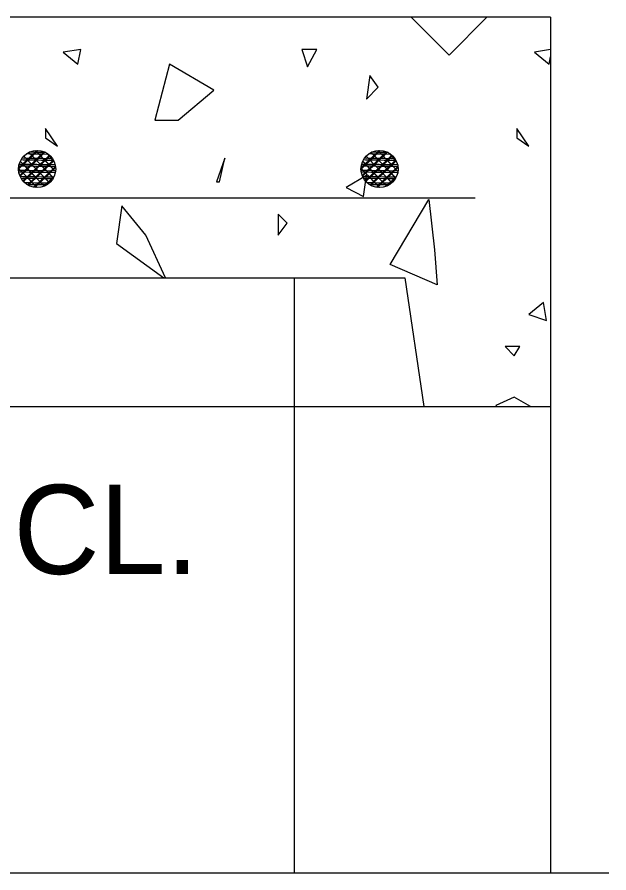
# Model space of a CAD drawing. Extents: x 26.41 to 33.74, y 20.66 to 30.6.
# Drawn here: x 32.985 to 33.383, y 27.258 to 27.834 of the extents above; entities that cross this region are included whole.
import ezdxf

# ---------------------------------------------------------------- set-up
doc = ezdxf.new("R2010")
doc.units = 0
for name, color, linetype in [('DETL-LINE', 7, 'Continuous'), ('DETL-NOTE', 7, 'Continuous'), ('DETL-PATT', 7, 'Continuous')]:
    doc.layers.add(name, color=color, linetype=linetype)

msp = doc.modelspace()

# ---------------------------------------------------------------- linework, layer by layer
at = {"layer": 'DETL-LINE'}
for p, q in [((33.34406, 27.83377), (31.7863, 27.83377)), ((33.34406, 27.83377), (33.34406, 27.25786)), ((32.99743, 27.74341), (32.98792, 27.73425)), ((32.9979, 27.74313), (32.98835, 27.73397)), ((32.9935, 27.74183), (33.00266, 27.73232)), ((32.99931, 27.74171), (33.00851, 27.7322)), ((33.22803, 27.74341), (33.21852, 27.73425)), ((33.22851, 27.74313), (33.21895, 27.73397)), ((33.2241, 27.74183), (33.23326, 27.73232)), ((33.22992, 27.74171), (33.23912, 27.7322)), ((32.98756, 27.73613), (32.99672, 27.72658)), ((32.99735, 27.73759), (32.9878, 27.72839)), ((32.99778, 27.73727), (32.98827, 27.72812)), ((33.00218, 27.73735), (32.98894, 27.73759)), ((33.00222, 27.73853), (32.98898, 27.73877)), ((32.99051, 27.73896), (32.99971, 27.72945)), ((33.0003, 27.74046), (32.99078, 27.73126)), ((33.00077, 27.74014), (32.99122, 27.73098)), ((33.00631, 27.73727), (32.99306, 27.73751)), ((33.00635, 27.73845), (32.9931, 27.73869)), ((32.99338, 27.73602), (33.00258, 27.72646)), ((33.00317, 27.73751), (32.99365, 27.72827)), ((33.00364, 27.73719), (32.99405, 27.728)), ((32.99633, 27.73885), (33.00552, 27.72933)), ((33.00615, 27.74038), (32.99664, 27.73114)), ((33.00659, 27.74006), (32.99703, 27.73087)), ((32.9992, 27.73594), (33.00839, 27.72635)), ((33.00902, 27.73739), (32.99947, 27.72819)), ((33.00942, 27.73708), (32.9999, 27.72788)), ((33.21817, 27.73613), (33.22733, 27.72658)), ((33.22795, 27.73759), (33.2184, 27.72839)), ((33.22839, 27.73727), (33.21888, 27.72812)), ((33.23279, 27.73735), (33.21954, 27.73759)), ((33.23283, 27.73853), (33.21958, 27.73877)), ((33.22112, 27.73896), (33.23031, 27.72945)), ((33.2309, 27.74046), (33.22139, 27.73126)), ((33.23137, 27.74014), (33.22182, 27.73098)), ((33.23692, 27.73727), (33.22367, 27.73751)), ((33.23696, 27.73845), (33.22371, 27.73869)), ((33.22399, 27.73602), (33.23318, 27.72646)), ((33.23377, 27.73751), (33.22426, 27.72827)), ((33.23424, 27.73719), (33.22465, 27.728)), ((33.22693, 27.73885), (33.23613, 27.72933)), ((33.23676, 27.74038), (33.22725, 27.73114)), ((33.23719, 27.74006), (33.22764, 27.73087)), ((33.2298, 27.73594), (33.239, 27.72635)), ((33.23963, 27.73739), (33.23008, 27.72819)), ((33.24002, 27.73708), (33.23051, 27.72788)), ((32.98744, 27.73028), (32.9966, 27.72076)), ((33.00207, 27.73028), (32.98882, 27.73051)), ((33.0021, 27.73322), (32.98886, 27.73346)), ((33.00214, 27.7344), (32.9889, 27.73464)), ((32.99043, 27.73315), (32.99959, 27.72359)), ((33.00022, 27.73464), (32.99067, 27.72544)), ((33.00065, 27.73433), (32.99114, 27.72513)), ((33.00619, 27.7302), (32.99295, 27.73043)), ((33.00623, 27.73315), (32.99299, 27.73338)), ((33.00627, 27.73433), (32.99303, 27.73456)), ((32.99326, 27.7302), (33.00246, 27.72065)), ((33.00309, 27.73165), (32.99354, 27.72249)), ((33.00352, 27.73134), (32.99397, 27.72214)), ((32.99621, 27.73307), (33.00545, 27.72348)), ((33.00604, 27.73452), (32.99652, 27.72532)), ((33.00647, 27.73421), (32.99692, 27.72501)), ((33.01032, 27.73012), (32.99707, 27.73036)), ((33.01036, 27.73307), (32.99711, 27.7333)), ((33.0104, 27.73425), (32.99715, 27.73448)), ((33.0089, 27.73153), (32.99935, 27.72238)), ((33.00934, 27.73122), (32.99979, 27.72206)), ((33.21805, 27.73028), (33.22721, 27.72076)), ((33.23267, 27.73028), (33.21943, 27.73051)), ((33.23271, 27.73322), (33.21946, 27.73346)), ((33.23275, 27.7344), (33.2195, 27.73464)), ((33.22104, 27.73315), (33.2302, 27.72359)), ((33.23082, 27.73464), (33.22127, 27.72544)), ((33.23126, 27.73433), (33.22174, 27.72513)), ((33.2368, 27.7302), (33.22355, 27.73043)), ((33.23684, 27.73315), (33.22359, 27.73338)), ((33.23688, 27.73433), (33.22363, 27.73456)), ((33.22387, 27.7302), (33.23306, 27.72065)), ((33.23369, 27.73165), (33.22414, 27.72249)), ((33.23413, 27.73134), (33.22457, 27.72214)), ((33.22682, 27.73307), (33.23605, 27.72348)), ((33.23664, 27.73452), (33.22713, 27.72532)), ((33.23707, 27.73421), (33.22752, 27.72501)), ((33.24093, 27.73012), (33.22768, 27.73036)), ((33.24097, 27.73307), (33.22772, 27.7333)), ((33.241, 27.73425), (33.22776, 27.73448)), ((33.23951, 27.73153), (33.22996, 27.72238)), ((33.23994, 27.73122), (33.23039, 27.72206)), ((33.00195, 27.72497), (32.9887, 27.72521)), ((33.00199, 27.72615), (32.98874, 27.72639)), ((33.00203, 27.7291), (32.98878, 27.72933)), ((33.00607, 27.72489), (32.99283, 27.72513)), ((33.00611, 27.72607), (32.99287, 27.72631)), ((33.00615, 27.72902), (32.99291, 27.72925)), ((33.00596, 27.72867), (32.99641, 27.71951)), ((33.00635, 27.72839), (32.99684, 27.71919)), ((33.01028, 27.72894), (32.99703, 27.72918)), ((33.23255, 27.72497), (33.21931, 27.72521)), ((33.23259, 27.72615), (33.21935, 27.72639)), ((33.23263, 27.7291), (33.21939, 27.72933)), ((33.23668, 27.72489), (33.22343, 27.72513)), ((33.23672, 27.72607), (33.22347, 27.72631)), ((33.23676, 27.72902), (33.22351, 27.72925)), ((33.23656, 27.72867), (33.22701, 27.71951)), ((33.23696, 27.72839), (33.22744, 27.71919)), ((33.24089, 27.72894), (33.22764, 27.72918)), ((33.00604, 27.72194), (32.99279, 27.72218)), ((33.23664, 27.72194), (33.2234, 27.72218)), ((33.29328, 27.71188), (32.55162, 27.71188)), ((31.86633, 27.65839), (33.24596, 27.65839)), ((33.17167, 27.25786), (33.17167, 27.65839)), ((33.24596, 27.65831), (33.25865, 27.5718)), ((31.85811, 27.57172), (33.25865, 27.5718)), ((33.25865, 27.5718), (33.34406, 27.5718)), ((32.72968, 27.25786), (33.38337, 27.25786))]:
    msp.add_line(p, q, dxfattribs=at)
for points in [[(32.99806, 27.74399), (32.9909, 27.73712)], [(33.00226, 27.74148), (32.99106, 27.74168)], [(32.99813, 27.74156), (32.99106, 27.74168)], [(32.99401, 27.74164), (32.99106, 27.74168)], [(32.99876, 27.74399), (32.99134, 27.7368)], [(32.99267, 27.7427), (32.99983, 27.73531)], [(33.00226, 27.74262), (32.99295, 27.74282)], [(32.99817, 27.7427), (32.99295, 27.74282)], [(32.99405, 27.74278), (32.99295, 27.74282)], [(33.00592, 27.7414), (32.99314, 27.74164)], [(33.00407, 27.74262), (32.99318, 27.74282)], [(33.00301, 27.74309), (32.99377, 27.73413)], [(32.99806, 27.74399), (32.99389, 27.73999)], [(33.00356, 27.74285), (32.99417, 27.73385)], [(32.99876, 27.74399), (32.99428, 27.73967)], [(33.00301, 27.74309), (32.99676, 27.737)], [(33.00356, 27.74285), (32.99715, 27.73668)], [(32.99719, 27.74396), (33.00277, 27.73814)], [(32.99719, 27.74396), (33.00564, 27.73519)], [(33.00592, 27.7414), (32.99727, 27.74156)], [(33.00407, 27.74262), (32.99731, 27.74274)], [(33.00592, 27.7414), (33.0014, 27.74148)], [(33.00407, 27.74262), (33.00144, 27.74266)], [(33.00438, 27.74246), (33.00576, 27.74101)], [(33.00438, 27.74246), (33.00863, 27.73806)], [(33.00438, 27.74246), (33.00945, 27.73719)], [(33.00517, 27.74164), (33.00945, 27.73719)], [(33.22866, 27.74399), (33.22151, 27.73712)], [(33.23287, 27.74148), (33.22167, 27.74168)], [(33.22874, 27.74156), (33.22167, 27.74168)], [(33.22461, 27.74164), (33.22167, 27.74168)], [(33.22937, 27.74399), (33.22194, 27.7368)], [(33.22328, 27.7427), (33.23043, 27.73531)], [(33.23287, 27.74262), (33.22355, 27.74282)], [(33.22878, 27.7427), (33.22355, 27.74282)], [(33.22465, 27.74278), (33.22355, 27.74282)], [(33.23652, 27.7414), (33.22375, 27.74164)], [(33.23468, 27.74262), (33.22379, 27.74282)], [(33.23361, 27.74309), (33.22438, 27.73413)], [(33.22866, 27.74399), (33.2245, 27.73999)], [(33.23417, 27.74285), (33.22477, 27.73385)], [(33.22937, 27.74399), (33.22489, 27.73967)], [(33.23361, 27.74309), (33.22737, 27.737)], [(33.23417, 27.74285), (33.22776, 27.73668)], [(33.2278, 27.74396), (33.23338, 27.73814)], [(33.2278, 27.74396), (33.23625, 27.73519)], [(33.23652, 27.7414), (33.22788, 27.74156)], [(33.23468, 27.74262), (33.22792, 27.74274)], [(33.23652, 27.7414), (33.232, 27.74148)], [(33.23468, 27.74262), (33.23204, 27.74266)], [(33.23499, 27.74246), (33.23637, 27.74101)], [(33.23499, 27.74246), (33.23924, 27.73806)], [(33.23499, 27.74246), (33.24006, 27.73719)], [(33.23578, 27.74164), (33.24006, 27.73719)], [(32.99491, 27.74026), (32.98583, 27.73153)], [(32.99192, 27.73739), (32.98583, 27.73153)], [(32.99448, 27.74058), (32.98587, 27.73224)], [(32.99149, 27.73771), (32.98587, 27.73224)], [(32.98697, 27.73672), (32.99385, 27.72957)], [(32.99806, 27.73743), (32.98744, 27.73763)], [(32.99393, 27.73751), (32.98744, 27.73763)], [(32.9898, 27.73759), (32.98744, 27.73763)], [(32.9981, 27.73857), (32.98815, 27.73877)], [(32.99397, 27.73865), (32.98815, 27.73877)], [(32.98984, 27.73873), (32.98815, 27.73877)], [(32.98933, 27.74018), (32.99684, 27.73244)], [(33.00942, 27.73719), (32.99719, 27.73743)], [(33.00871, 27.73837), (32.99723, 27.73861)], [(33.00662, 27.74081), (32.99959, 27.73401)], [(33.00702, 27.7405), (33.00002, 27.73374)], [(33.00942, 27.73719), (33.00132, 27.73735)], [(33.00871, 27.73837), (33.00136, 27.73853)], [(33.00218, 27.73877), (33.01063, 27.72996)], [(33.00922, 27.73755), (33.00246, 27.73106)], [(33.00945, 27.73712), (33.00289, 27.73075)], [(33.00505, 27.73582), (33.01063, 27.72996)], [(33.008, 27.73865), (33.00945, 27.73719)], [(33.22552, 27.74026), (33.21644, 27.73153)], [(33.22253, 27.73739), (33.21644, 27.73153)], [(33.22509, 27.74058), (33.21648, 27.73224)], [(33.2221, 27.73771), (33.21648, 27.73224)], [(33.21758, 27.73672), (33.22446, 27.72957)], [(33.22866, 27.73743), (33.21805, 27.73763)], [(33.22454, 27.73751), (33.21805, 27.73763)], [(33.22041, 27.73759), (33.21805, 27.73763)], [(33.2287, 27.73857), (33.21876, 27.73877)], [(33.22457, 27.73865), (33.21876, 27.73877)], [(33.22045, 27.73873), (33.21876, 27.73877)], [(33.21994, 27.74018), (33.22744, 27.73244)], [(33.24002, 27.73719), (33.2278, 27.73743)], [(33.23931, 27.73837), (33.22784, 27.73861)], [(33.23723, 27.74081), (33.2302, 27.73401)], [(33.23762, 27.7405), (33.23063, 27.73374)], [(33.24002, 27.73719), (33.23192, 27.73735)], [(33.23931, 27.73837), (33.23196, 27.73853)], [(33.23279, 27.73877), (33.24124, 27.72996)], [(33.23983, 27.73755), (33.23306, 27.73106)], [(33.24006, 27.73712), (33.2335, 27.73075)], [(33.23566, 27.73582), (33.24124, 27.72996)], [(33.23861, 27.73865), (33.24006, 27.73719)], [(32.98898, 27.73452), (32.98583, 27.73153)], [(32.98583, 27.73193), (32.99086, 27.7267)], [(32.98583, 27.73193), (32.99373, 27.72371)], [(32.98599, 27.73165), (32.98583, 27.73153)], [(32.98854, 27.73484), (32.98587, 27.73224)], [(32.99794, 27.73036), (32.98587, 27.73055)], [(32.99381, 27.73043), (32.98587, 27.73055)], [(32.98968, 27.73047), (32.98587, 27.73055)], [(32.99798, 27.7333), (32.98603, 27.7335)], [(32.99385, 27.73338), (32.98603, 27.7335)], [(32.98972, 27.73346), (32.98603, 27.7335)], [(32.99802, 27.73448), (32.98626, 27.73468)], [(32.99389, 27.73452), (32.98626, 27.73468)], [(32.98976, 27.7346), (32.98626, 27.73468)], [(32.99436, 27.73472), (32.98658, 27.72725)], [(32.99137, 27.73189), (32.98658, 27.72725)], [(32.99479, 27.7344), (32.98681, 27.72674)], [(32.99185, 27.73153), (32.98681, 27.72674)], [(32.99723, 27.73177), (32.9887, 27.72356)], [(32.99766, 27.73146), (32.98906, 27.72316)], [(32.99908, 27.73008), (33.00662, 27.72226)], [(33.01067, 27.73012), (33.0012, 27.73028)], [(33.01067, 27.73307), (33.00124, 27.73322)], [(33.01048, 27.73425), (33.00128, 27.7344)], [(33.00207, 27.73295), (33.00922, 27.72552)], [(33.01063, 27.73319), (33.00234, 27.72525)], [(33.01071, 27.73256), (33.00277, 27.72493)], [(33.00493, 27.72996), (33.00922, 27.72552)], [(33.01063, 27.73319), (33.00533, 27.72808)], [(33.01071, 27.73256), (33.00576, 27.7278)], [(33.00792, 27.73283), (33.01063, 27.72996)], [(33.21958, 27.73452), (33.21644, 27.73153)], [(33.21644, 27.73193), (33.22147, 27.7267)], [(33.21644, 27.73193), (33.22434, 27.72371)], [(33.2166, 27.73165), (33.21644, 27.73153)], [(33.21915, 27.73484), (33.21648, 27.73224)], [(33.22854, 27.73036), (33.21648, 27.73055)], [(33.22442, 27.73043), (33.21648, 27.73055)], [(33.22029, 27.73047), (33.21648, 27.73055)], [(33.22858, 27.7333), (33.21663, 27.7335)], [(33.22446, 27.73338), (33.21663, 27.7335)], [(33.22033, 27.73346), (33.21663, 27.7335)], [(33.22862, 27.73448), (33.21687, 27.73468)], [(33.2245, 27.73452), (33.21687, 27.73468)], [(33.22037, 27.7346), (33.21687, 27.73468)], [(33.22497, 27.73472), (33.21719, 27.72725)], [(33.22198, 27.73189), (33.21719, 27.72725)], [(33.2254, 27.7344), (33.21742, 27.72674)], [(33.22245, 27.73153), (33.21742, 27.72674)], [(33.22784, 27.73177), (33.21931, 27.72356)], [(33.22827, 27.73146), (33.21966, 27.72316)], [(33.22968, 27.73008), (33.23723, 27.72226)], [(33.24128, 27.73012), (33.23181, 27.73028)], [(33.24128, 27.73307), (33.23185, 27.73322)], [(33.24108, 27.73425), (33.23189, 27.7344)], [(33.23267, 27.73295), (33.23983, 27.72552)], [(33.24124, 27.73319), (33.23295, 27.72525)], [(33.24132, 27.73256), (33.23338, 27.72493)], [(33.23554, 27.72996), (33.23983, 27.72552)], [(33.24124, 27.73319), (33.23593, 27.72808)], [(33.24132, 27.73256), (33.23637, 27.7278)], [(33.23853, 27.73283), (33.24124, 27.72996)], [(32.9979, 27.72918), (32.98603, 27.72937)], [(32.99377, 27.72925), (32.98603, 27.72937)], [(32.98964, 27.72933), (32.98603, 27.72937)], [(32.98843, 27.72902), (32.98658, 27.72725)], [(32.98886, 27.7287), (32.98681, 27.72674)], [(32.99786, 27.72623), (32.98693, 27.72642)], [(32.99373, 27.72631), (32.98693, 27.72642)], [(32.98961, 27.72635), (32.98693, 27.72642)], [(32.99782, 27.72505), (32.98756, 27.72525)], [(32.99369, 27.72513), (32.98756, 27.72525)], [(32.98957, 27.72521), (32.98756, 27.72525)], [(32.99424, 27.7289), (32.9887, 27.72356)], [(32.9913, 27.72603), (32.9887, 27.72356)], [(32.99468, 27.72863), (32.98906, 27.72316)], [(32.99173, 27.72576), (32.98906, 27.72316)], [(32.99031, 27.72733), (32.99821, 27.71907)], [(33.0001, 27.72878), (32.99189, 27.72084)], [(32.99711, 27.72591), (32.99189, 27.72084)], [(33.00053, 27.72851), (32.99236, 27.72061)], [(32.99755, 27.72564), (32.99236, 27.72061)], [(32.99318, 27.72434), (32.99821, 27.71907)], [(32.99613, 27.72721), (33.00305, 27.72002)], [(33.00297, 27.7258), (32.99613, 27.71927)], [(33.0034, 27.72552), (32.99684, 27.71919)], [(33.00879, 27.72485), (32.99696, 27.72505)], [(33.00945, 27.72599), (32.997, 27.72623)], [(32.999, 27.72422), (33.00305, 27.72002)], [(33.00879, 27.72485), (33.00108, 27.72497)], [(33.00945, 27.72599), (33.00112, 27.72615)], [(33.01048, 27.72894), (33.00116, 27.7291)], [(33.00195, 27.72709), (33.00662, 27.72226)], [(33.00977, 27.72666), (33.00273, 27.7199)], [(33.00883, 27.72572), (33.00273, 27.7199)], [(33.0091, 27.72529), (33.00415, 27.72053)], [(33.0091, 27.72529), (33.00415, 27.72053)], [(33.00977, 27.72666), (33.00521, 27.72226)], [(33.0091, 27.72529), (33.00564, 27.72194)], [(33.0078, 27.72698), (33.00922, 27.72552)], [(33.00977, 27.72666), (33.0082, 27.72513)], [(33.0091, 27.72529), (33.00863, 27.72481)], [(33.22851, 27.72918), (33.21663, 27.72937)], [(33.22438, 27.72925), (33.21663, 27.72937)], [(33.22025, 27.72933), (33.21663, 27.72937)], [(33.21903, 27.72902), (33.21719, 27.72725)], [(33.21946, 27.7287), (33.21742, 27.72674)], [(33.22847, 27.72623), (33.21754, 27.72642)], [(33.22434, 27.72631), (33.21754, 27.72642)], [(33.22021, 27.72635), (33.21754, 27.72642)], [(33.22843, 27.72505), (33.21817, 27.72525)], [(33.2243, 27.72513), (33.21817, 27.72525)], [(33.22017, 27.72521), (33.21817, 27.72525)], [(33.22485, 27.7289), (33.21931, 27.72356)], [(33.2219, 27.72603), (33.21931, 27.72356)], [(33.22528, 27.72863), (33.21966, 27.72316)], [(33.22233, 27.72576), (33.21966, 27.72316)], [(33.22092, 27.72733), (33.22882, 27.71907)], [(33.23071, 27.72878), (33.22249, 27.72084)], [(33.22772, 27.72591), (33.22249, 27.72084)], [(33.23114, 27.72851), (33.22296, 27.72061)], [(33.22815, 27.72564), (33.22296, 27.72061)], [(33.22379, 27.72434), (33.22882, 27.71907)], [(33.22674, 27.72721), (33.23365, 27.72002)], [(33.23358, 27.7258), (33.22674, 27.71927)], [(33.23401, 27.72552), (33.22744, 27.71919)], [(33.23939, 27.72485), (33.22756, 27.72505)], [(33.24006, 27.72599), (33.2276, 27.72623)], [(33.22961, 27.72422), (33.23365, 27.72002)], [(33.23939, 27.72485), (33.23169, 27.72497)], [(33.24006, 27.72599), (33.23173, 27.72615)], [(33.24108, 27.72894), (33.23177, 27.7291)], [(33.23255, 27.72709), (33.23723, 27.72226)], [(33.24038, 27.72666), (33.23334, 27.7199)], [(33.23943, 27.72572), (33.23334, 27.7199)], [(33.23971, 27.72529), (33.23475, 27.72053)], [(33.23971, 27.72529), (33.23475, 27.72053)], [(33.24038, 27.72666), (33.23582, 27.72226)], [(33.23971, 27.72529), (33.23625, 27.72194)], [(33.23841, 27.72698), (33.23983, 27.72552)], [(33.24038, 27.72666), (33.2388, 27.72513)], [(33.23971, 27.72529), (33.23924, 27.72481)], [(33.00191, 27.72202), (32.99, 27.72222)], [(32.99778, 27.7221), (32.99, 27.72222)], [(32.99365, 27.72218), (32.99, 27.72222)], [(33.00187, 27.72084), (32.99161, 27.72104)], [(32.99774, 27.72092), (32.99161, 27.72104)], [(32.99361, 27.721), (32.99161, 27.72104)], [(32.99413, 27.72304), (32.99189, 27.72084)], [(32.9946, 27.72277), (32.99236, 27.72061)], [(33.00458, 27.7208), (32.99275, 27.721)], [(32.99601, 27.72135), (32.99821, 27.71907)], [(32.99998, 27.72293), (32.99613, 27.71927)], [(32.997, 27.7201), (32.99613, 27.71927)], [(33.00041, 27.72265), (32.99684, 27.71919)], [(32.99747, 27.71978), (32.99684, 27.71919)], [(33.00458, 27.7208), (32.99688, 27.72092)], [(33.00623, 27.72194), (32.99692, 27.7221)], [(33.00458, 27.7208), (33.001, 27.72084)], [(33.00623, 27.72194), (33.00104, 27.72202)], [(33.00187, 27.72124), (33.00305, 27.72002)], [(33.00584, 27.72285), (33.00273, 27.7199)], [(33.00285, 27.71998), (33.00273, 27.7199)], [(33.00623, 27.72253), (33.00415, 27.72053)], [(33.00482, 27.72411), (33.00662, 27.72226)], [(33.23251, 27.72202), (33.2206, 27.72222)], [(33.22839, 27.7221), (33.2206, 27.72222)], [(33.22426, 27.72218), (33.2206, 27.72222)], [(33.23248, 27.72084), (33.22222, 27.72104)], [(33.22835, 27.72092), (33.22222, 27.72104)], [(33.22422, 27.721), (33.22222, 27.72104)], [(33.22473, 27.72304), (33.22249, 27.72084)], [(33.2252, 27.72277), (33.22296, 27.72061)], [(33.23519, 27.7208), (33.22336, 27.721)], [(33.22662, 27.72135), (33.22882, 27.71907)], [(33.23059, 27.72293), (33.22674, 27.71927)], [(33.2276, 27.7201), (33.22674, 27.71927)], [(33.23102, 27.72265), (33.22744, 27.71919)], [(33.22807, 27.71978), (33.22744, 27.71919)], [(33.23519, 27.7208), (33.22748, 27.72092)], [(33.23684, 27.72194), (33.22752, 27.7221)], [(33.23519, 27.7208), (33.23161, 27.72084)], [(33.23684, 27.72194), (33.23165, 27.72202)], [(33.23248, 27.72124), (33.23365, 27.72002)], [(33.23644, 27.72285), (33.23334, 27.7199)], [(33.23346, 27.71998), (33.23334, 27.7199)], [(33.23684, 27.72253), (33.23475, 27.72053)], [(33.23542, 27.72411), (33.23723, 27.72226)]]:
    msp.add_lwpolyline(points, dxfattribs=at)
for centre in [(32.9983, 27.73153), (33.2289, 27.73153)]:
    msp.add_circle(centre, 0.01249, dxfattribs=at)
at = {"layer": 'DETL-PATT'}
for points in [[(33.30122, 27.83377), (33.27571, 27.80826), (33.2502, 27.83377)], [(33.34406, 27.81188), (33.33325, 27.81015), (33.34316, 27.80213), (33.34406, 27.80704)], [(33.08465, 27.65839), (33.07148, 27.68704), (33.05544, 27.70685), (33.05167, 27.68138), (33.08366, 27.65839)], [(33.33046, 27.5718), (33.31958, 27.57809), (33.30731, 27.57243), (33.3079, 27.5718)]]:
    msp.add_lwpolyline(points, dxfattribs=at)
for points in [[(33.01582, 27.81015), (33.02573, 27.80213), (33.02761, 27.81203)], [(33.17666, 27.81203), (33.18043, 27.80024), (33.18657, 27.81203)], [(33.09318, 27.76439), (33.11723, 27.78468), (33.08752, 27.80213), (33.07761, 27.76439)], [(33.22241, 27.79458), (33.22005, 27.77854), (33.22807, 27.78656)], [(33.00403, 27.75873), (33.00403, 27.7526), (33.01205, 27.74694)], [(33.32146, 27.75873), (33.32146, 27.7526), (33.32948, 27.74694)], [(33.11912, 27.72289), (33.121, 27.72289), (33.12478, 27.73892)], [(33.20638, 27.71911), (33.21817, 27.71298), (33.22005, 27.72713)], [(33.26581, 27.67714), (33.26769, 27.65355), (33.23609, 27.66723), (33.26203, 27.7111)], [(33.16062, 27.70119), (33.16062, 27.68704), (33.16676, 27.69506)], [(33.33939, 27.64176), (33.32948, 27.63374), (33.34127, 27.6295)], [(33.31344, 27.61205), (33.31958, 27.60591), (33.32335, 27.61205)]]:
    msp.add_lwpolyline(points, close=True, dxfattribs=at)

# ---------------------------------------------------------------- texts
at = {"layer": 'DETL-NOTE'}
msp.add_text('CL.', height=0.05998, dxfattribs=at).set_placement((32.98233, 27.45903))

doc.saveas('drawing.dxf')
